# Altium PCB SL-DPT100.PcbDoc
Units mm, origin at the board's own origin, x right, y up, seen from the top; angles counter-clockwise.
Board outline 73.2 x 55.1 mm, 2 copper layers (Top Layer, Bottom Layer); 172 components, 163 nets, 580 pads, 6 vias.
Unrouted connection lines stored in the file: 382.
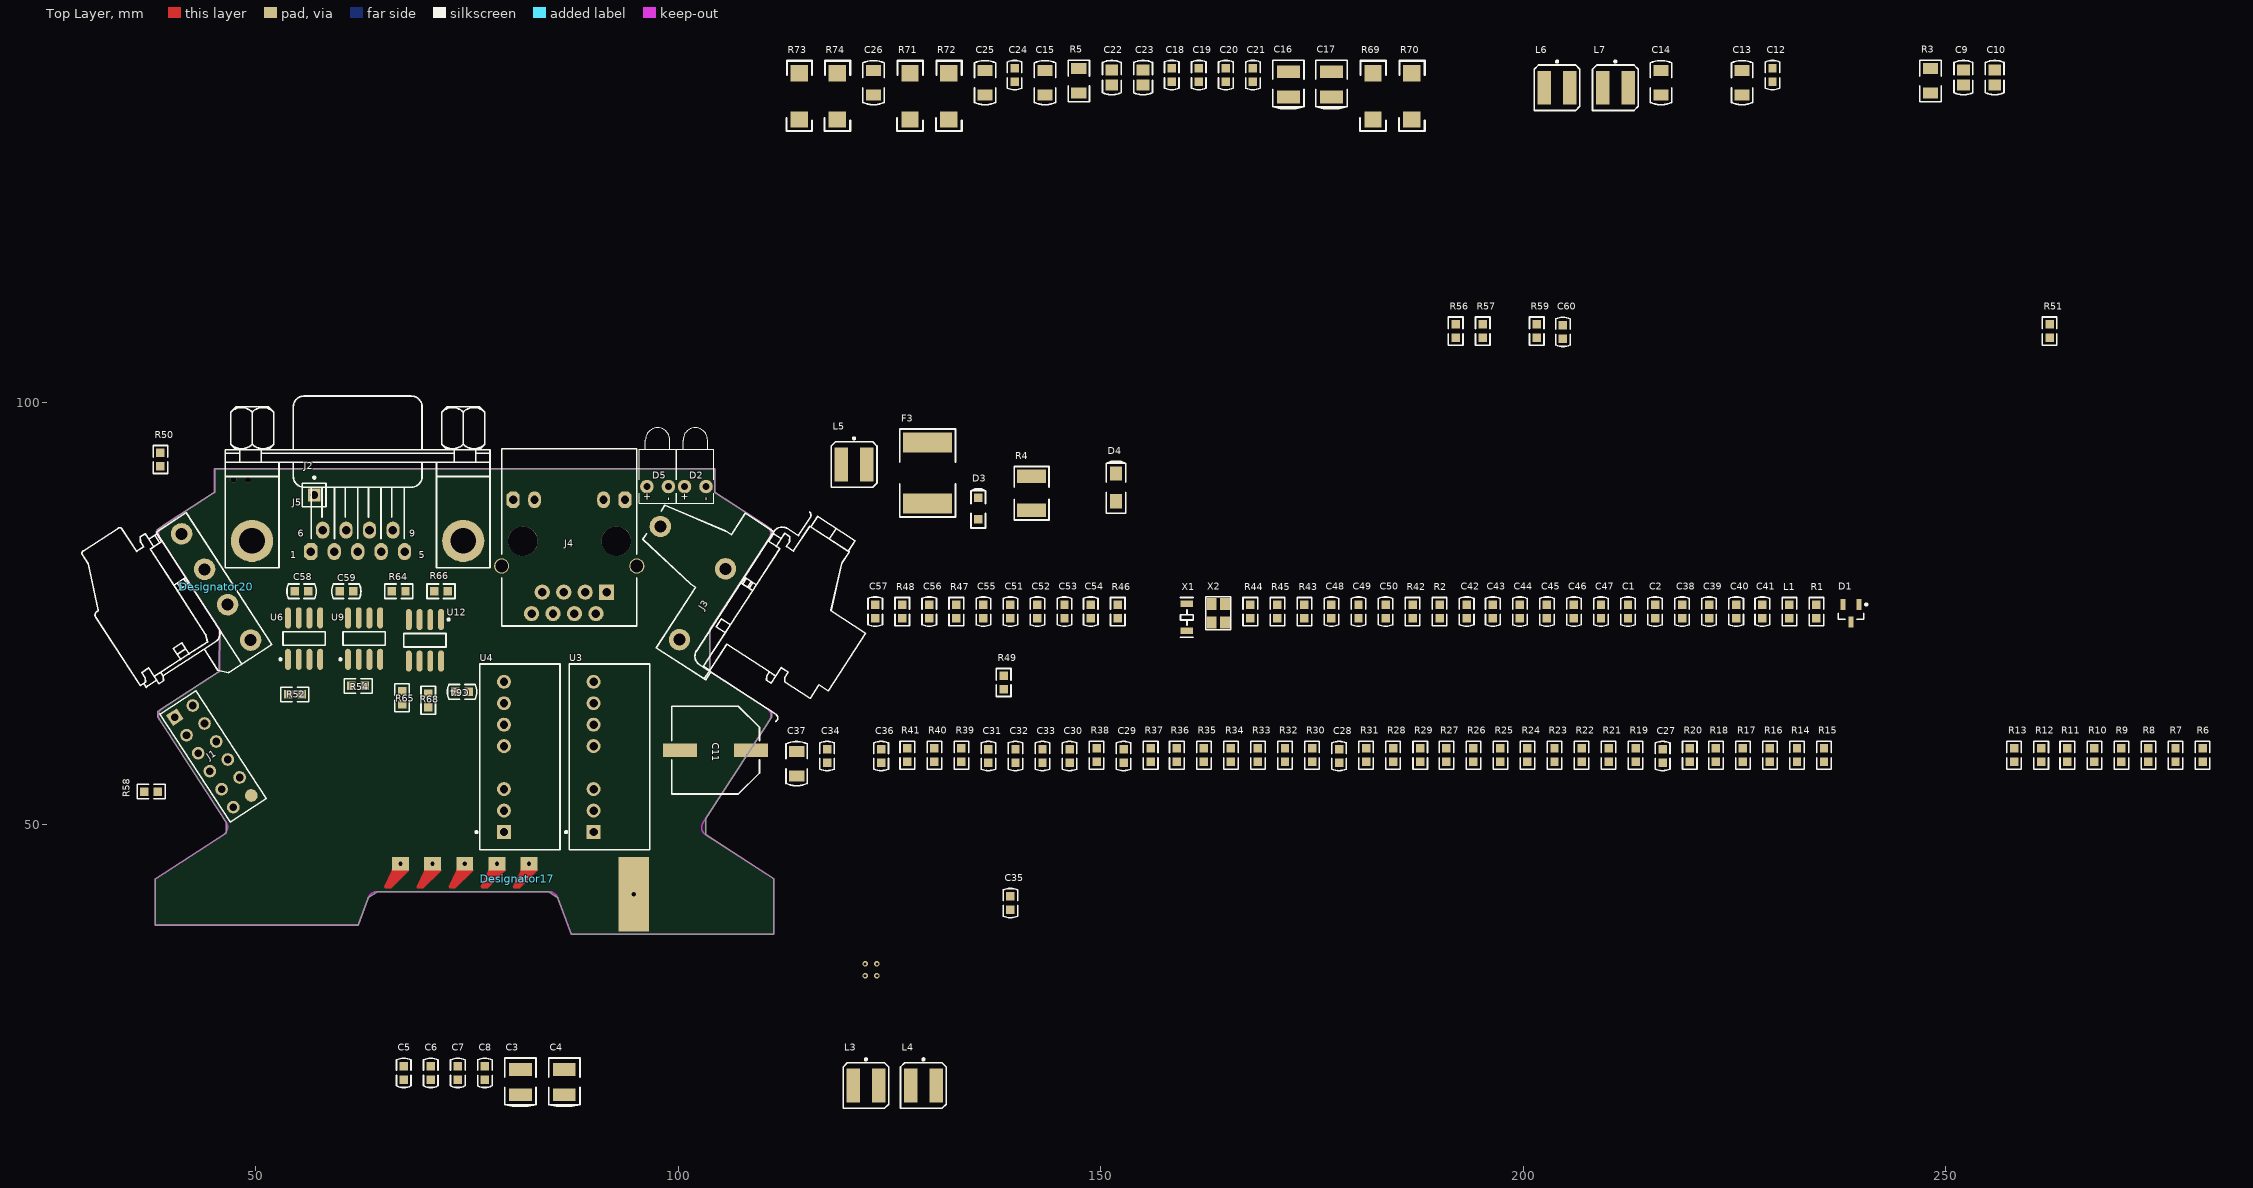
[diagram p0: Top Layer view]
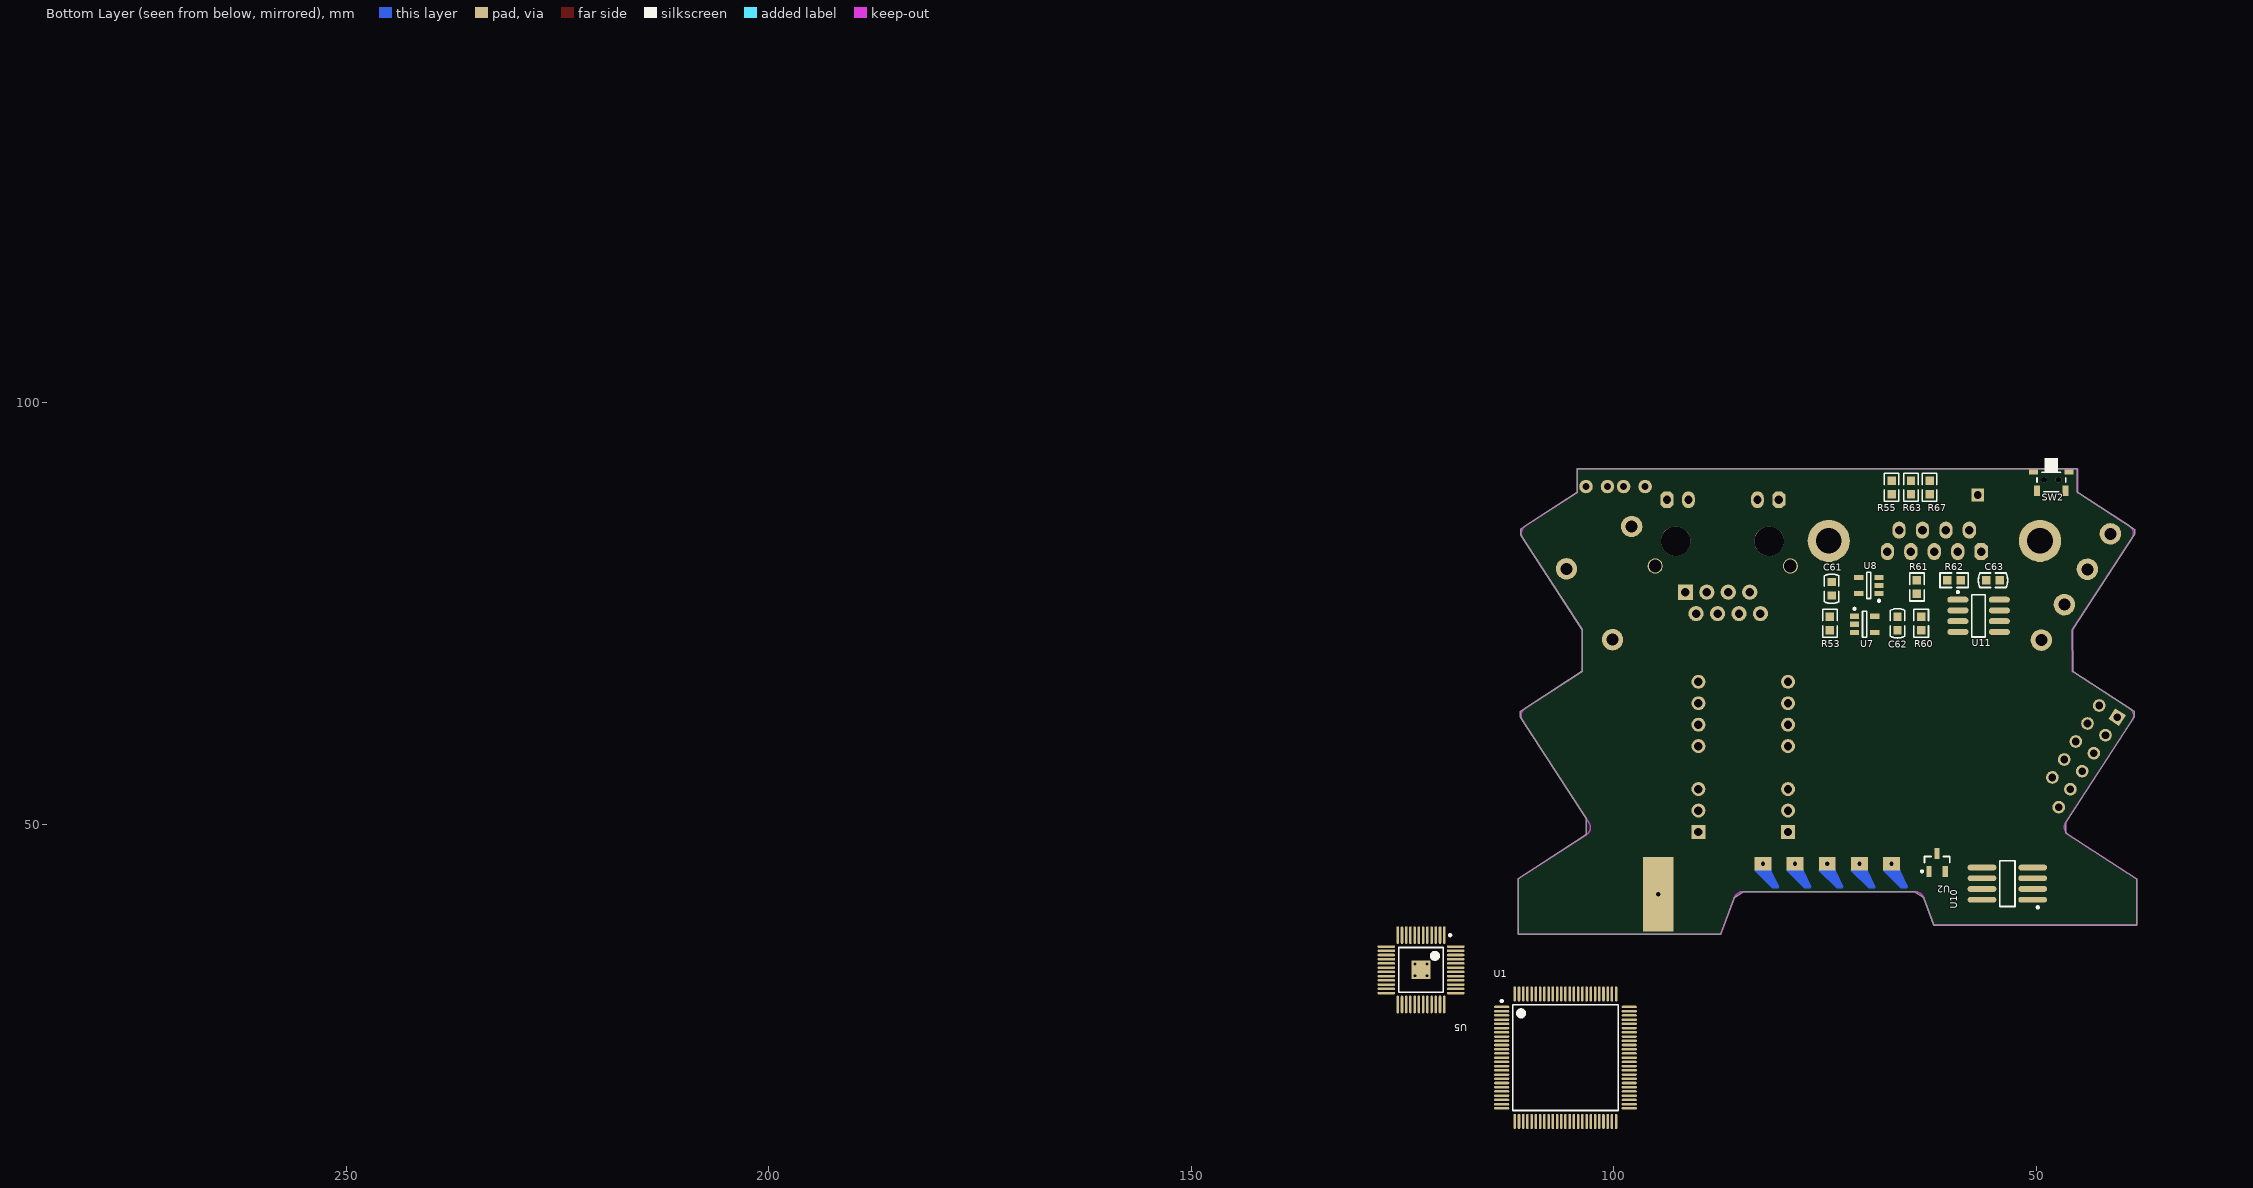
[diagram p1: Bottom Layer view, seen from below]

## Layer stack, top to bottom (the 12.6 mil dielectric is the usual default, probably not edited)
Top Layer: signal copper 0.0356
Dielectric: dielectric 0.32, FR-4, Dk 4.8
Bottom Layer: signal copper 0.0356

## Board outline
64.379,42.05 63.285,41.32 62.11,38.1 38.1,38.1 38.1,43.548 46.5,49 46.516,50.15 38.4,62.7 38.4,63.4 45.686,68.122 45.697,73.048 38.3,84.4 38.3,84.9 45.097,89.304 45.1,92.1 104.3,92.1 104.303,89.304 111,84.965 111,84.247 103.703,73.048 103.714,68.122 111.05,63.375 111.05,62.725 103.247,50.731 103.246,48.778 111.299,43.548 111.3,37 87.35,37 85.722,41.322 84.627,42.05

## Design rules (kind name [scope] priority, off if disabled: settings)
Clearance Clearance_U1_U5 [(InComponent(U1) Or InComponent(U5)) And IsComponentPad] p1: gap=0.2
Clearance Clearance_Pad_K [IsComponentPad vs OnLayer('Keep-Out Layer')] p2: gap=0.01
Clearance [All] p3: gap=0.254
HoleSize [All] p1: absolutevalues=TRUE maxlimit=25.4 minlimit=0.025 maxpercent=80.000 minpercent=20.000
PolygonConnect [All] p1: connectstyle=Relief reliefconductorwidth=0.254 reliefentries=4 polygonreliefangle="90 Angle"
RoutingVias [All] p1: holewidth=0.33 width=0.66 viastyle="Through Hole" minholewidth=0.305 minwidth=0.61 maxholewidth=3.048 maxwidth=6.096
SilkToSilkClearance [All] p1: silktosilkclearance=0.102
SilkscreenOverComponentPads SilkscreenOverComponentPads_1 [All] p1: minsilkscreentomaskgap=0.01
SilkscreenOverComponentPads [All] p2: minsilkscreentomaskgap=0.254
SolderMaskExpansion [All] p1: expansion=0.102
Width [All] p1: maxlimit=2.54 minlimit=0.152 preferedwidth=0.254
25 further rules are at their usual default settings.

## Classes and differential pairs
net class PE[0..15]: PE0 PE1 PE2 PE3 PE4 PE5 PE6 PE7 PE8 PE9 PE10 PE11 PE12 PE13 PE14 PE15
net class PD[0..15]: PD0 PD1 PD2 PD3 PD4 PD5 PD6 PD7 PD8 PD9 PD10 PD11 PD12 PD13 PD14 PD15
net class PC[0..15]: PC0 PC1 PC2 PC3 PC4 PC5 PC6 PC7 PC8 PC9 PC10 PC11 PC12 PC13 PC14 PC15
net class PB[0..15]: PB0 PB1 PB2 PB3 PB4 PB5 PB6 PB7 PB8 PB9 PB10 PB11 PB12 PB13 PB14 PB15
net class PA[0..15]: PA0 PA1 PA2 PA3 PA4 PA5 PA6 PA7 PA8 PA9 PA10 PA11 PA12 PA13 PA14 PA15
component class Power: C3 C4 C5 C6 C7 C8 C9 C10 C11 C12 C13 C14 C15 C16 C17 C18 C19 C20 C21 C22 C23 C24 C25 C26 D3 D4 F3 J3 L3 L4 L5 L6 L7 R3 R4 R5 R69 R70 R71 R72 R73 R74 U3 U4
component class MCU: C1 C2 C38 C39 C40 C41 C42 C43 C44 C45 C46 C47 C48 C49 C50 C51 C52 C53 C54 C55 C56 C57 D1 J1 L1 R1 R2 R42 R43 R44 R45 R46 R47 R48 R49 U2 X1 X2
component class MCU_1: C58 C59 C60 C61 C62 C63 C64 D2 D5 J2 J5 R50 R51 R52 R53 R54 R55 R56 R57 R58 R59 R60 R61 R62 R63 R64 R65 R66 R67 R68 SW2 U1 U6 U7 U8 U9 U10 U11 U12
component class Ethernet: C27 C28 C29 C30 C31 C32 C33 C34 C35 C36 C37 J4 R6 R7 R8 R9 R10 R11 R12 R13 R14 R15 R16 R17 R18 R19 R20 R21 R22 R23 R24 R25 R26 R27 R28 R29 R30 R31 R32 R33 R34 R35 R36 R37 R38 R39 R40 R41 U5

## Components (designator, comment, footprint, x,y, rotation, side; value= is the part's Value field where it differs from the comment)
C1 "0.1uF" C1608(0603) 212.4,75.2 r90 top
C2 "0.1uF" C1608(0603) 215.6,75.2 r90 top
C3 "33uF" C3528(B) 81.299,19.5 r90 top
C4 "33uF" C3528(B) 86.499,19.5 r90 top
C5 "0.01uF" C1608(0603) 67.499,20.6 r90 top
C6 "0.1uF" C1608(0603) 70.699,20.6 r90 top
C7 "0.01uF" C1608(0603) 73.899,20.6 r90 top
C8 "0.1uF" C1608(0603) 77.099,20.6 r90 top
C9 "4.7uF/50V" C2012(0805) 252.099,138.4 r90 top
C10 "4.7uF/50V" C2012(0805) 255.799,138.4 r90 top
C11 "330uF/50V" CAPMP10X120 104.4,58.8 r180 top
C12 "0.1uF" C1608(0603) 229.5,138.7 r90 top
C13 "10uF/50V" C3216(1206) 225.9,137.8 r90 top
C14 "1000pF/2KV" C3216(1206) 216.3,137.8 r90 top
C15 "1000pF/2KV" C3216(1206) 143.4,137.8 r90 top
C16 "33uF" C3528(B) 172.2,137.6 r90 top
C17 "33uF" C3528(B) 177.3,137.6 r90 top
C18 "0.01uF" C1608(0603) 158.4,138.7 r90 top
C19 "0.1uF" C1608(0603) 161.6,138.7 r90 top
C20 "0.01uF" C1608(0603) 164.8,138.7 r90 top
C21 "0.1uF" C1608(0603) 168,138.7 r90 top
C22 "4.7uF/50V" C2012(0805) 151.3,138.4 r90 top
C23 "4.7uF/50V" C2012(0805) 155,138.4 r90 top
C24 "0.1uF" C1608(0603) 139.8,138.7 r90 top
C25 "10uF/50V" C3216(1206) 136.3,137.8 r90 top
C26 "1000pF/2KV" C3216(1206) 123.1,137.8 r90 top
C27 "0.1uF" C1608(0603) 216.5,58.1 r90 top
C28 "0.1uF" C1608(0603) 178.2,58.1 r90 top
C29 "0.1uF" C1608(0603) 152.7,58.1 r90 top
C30 "22pF" C1608(0603) 146.3,58.1 r90 top
C31 "0.1uF" C1608(0603) 136.7,58.1 r90 top
C32 "0.1uF" C1608(0603) 139.9,58.1 r90 top
C33 "0.1uF" C1608(0603) 143.1,58.1 r90 top
C34 "0.1uF" C1608(0603) 117.6,58.1 r90 top
C35 "0.1uF" C1608(0603) 139.3,40.7 r90 top
C36 "0.1uF" C1608(0603) 124,58.1 r90 top
C37 "10uF" C3216(1206) 114,57.2 r90 top
C38 "0.1uF" C1608(0603) 218.8,75.2 r90 top
C39 "1uF" C1608(0603) 222,75.2 r90 top
C40 "0.1uF" C1608(0603) 225.2,75.2 r90 top
C41 "1uF" C1608(0603) 228.3,75.2 r90 top
C42 "0.1uF" C1608(0603) 193.3,75.2 r90 top
C43 "0.1uF" C1608(0603) 196.4,75.2 r90 top
C44 "0.1uF" C1608(0603) 199.6,75.2 r90 top
C45 "0.1uF" C1608(0603) 202.8,75.2 r90 top
C46 "0.1uF" C1608(0603) 206,75.2 r90 top
C47 "0.1uF" C1608(0603) 209.2,75.2 r90 top
C48 "0.1uF" C1608(0603) 177.3,75.2 r90 top
C49 "2.2uF" C1608(0603) 180.5,75.2 r90 top
C50 "2.2uF" C1608(0603) 183.7,75.2 r90 top
C51 "22pF" C1608(0603) 139.3,75.2 r90 top
C52 "22pF" C1608(0603) 142.5,75.2 r90 top
C53 "22pF" C1608(0603) 145.7,75.2 r90 top
C54 "22pF" C1608(0603) 148.8,75.2 r90 top
C55 "0.1uF" C1608(0603) 136.1,75.2 r90 top
C56 "1uF" C1608(0603) 129.7,75.2 r90 top
C57 "0.1uF" C1608(0603) 123.3,75.2 r90 top
C58 "0.1uF" C1608(0603) 55.4,77.6 r0 top
C59 "0.1uF" C1608(0603) 60.7,77.6 r180 top
C60 "0.1uF" C1608(0603) 204.7,108.3 r90 top
C61 "0.1uF" C1608(0603) 74.2,77.9 r270 bottom
C62 "0.1uF" C1608(0603) 66.4,73.81 r270 bottom
C63 "0.1uF" C1608(0603) 55.1,78.9 r0 bottom
C64 "0.1uF" C1608(0603) 74.4,65.7 r0 top
D1 "BAT54C" SOT23-3_N 238.8,75 r90 top
D2 "LED0" LED-1 102,90 r90 top locked
D3 "1A/30V" SOD323 135.5,87.4 r90 top
D4 "SMF24A" SOD123 151.8,89.9 r90 top
D5 "LED0" LED-1 97.55,90 r90 top locked
Designator17 "Comment" "ME22.5 TBUS1.5/5" 74.719,42.05 r0 top locked
Designator20 "Comment" "MKDSO 2.5/4-L" 45.285,78.11 r33 top locked
F3 "SMD2920P050" R7555(2920) 129.5,91.6 r90 top
J1 "H2.54 6X2" HDR2X6 40.4,62.7 r303 top locked
J2 "Plug" PIN1 56.9,89 r0 top
J3 "Header 3" "MKDSO2.5 HV/3R-7.5" 105.58,80.26 r327 top locked
J4 "HR911105A" RJ45-LED 91.5,77.5 r0 top locked
J5 "D Connector 9" DB9F 56.5,82.3 r0 top locked
L1 "FCM1608KF-601T03" R1608(0603) 231.5,75.2 r90 top
L3 "10uH/1A" L4040 122.199,19.1 r0 top
L4 "10uH/1A" L4040 128.999,19.1 r0 top
L5 "68uH/0.5A" L4040 120.8,92.6 r0 top
L6 "10uH/1A" L4040 204,137.2 r0 top
L7 "10uH/1A" L4040 210.9,137.2 r0 top
R1 "0R" R1608(0603) 234.7,75.2 r90 top
R2 "1K" R1608(0603) 190.1,75.2 r90 top
R3 "82R" R3216(1206) 248.2,138 r90 top
R4 "MLV1812NA030" R4532(1812) 141.8,89.2 r90 top
R5 "82R" R3216(1206) 147.4,138 r90 top
R6 "33R" R1608(0603) 280.399,58.2 r90 top
R7 "33R" R1608(0603) 277.199,58.2 r90 top
R8 "33R" R1608(0603) 273.999,58.2 r90 top
R9 "33R" R1608(0603) 270.799,58.2 r90 top
R10 "33R" R1608(0603) 267.599,58.2 r90 top
R11 "33R" R1608(0603) 264.399,58.2 r90 top
R12 "33R" R1608(0603) 261.299,58.2 r90 top
R13 "33R" R1608(0603) 258.099,58.2 r90 top
R14 "33R" R1608(0603) 232.4,58.2 r90 top
R15 "49.9R" R1608(0603) 235.6,58.2 r90 top
R16 "33R" R1608(0603) 229.2,58.2 r90 top
R17 "33R" R1608(0603) 226,58.2 r90 top
R18 "33R" R1608(0603) 222.8,58.2 r90 top
R19 "2.2K" R1608(0603) 213.3,58.2 r90 top
R20 "49.9R" R1608(0603) 219.7,58.2 r90 top
R21 "33R" R1608(0603) 210.1,58.2 r90 top
R22 "2.2K" R1608(0603) 206.9,58.2 r90 top
R23 "2.2K" R1608(0603) 203.7,58.2 r90 top
R24 "49.9R" R1608(0603) 200.5,58.2 r90 top
R25 "1K" R1608(0603) 197.3,58.2 r90 top
R26 "2.2K" R1608(0603) 194.1,58.2 r90 top
R27 "33R" R1608(0603) 190.9,58.2 r90 top
R28 "33R" R1608(0603) 184.6,58.2 r90 top
R29 "2.2K" R1608(0603) 187.8,58.2 r90 top
R30 "33R" R1608(0603) 175,58.2 r90 top
R31 "49.9R" R1608(0603) 181.4,58.2 r90 top
R32 "33R" R1608(0603) 171.8,58.2 r90 top
R33 "2.2K" R1608(0603) 168.6,58.2 r90 top
R34 "2.2K" R1608(0603) 165.4,58.2 r90 top
R35 "1K" R1608(0603) 162.2,58.2 r90 top
R36 "33R" R1608(0603) 159,58.2 r90 top
R37 "33R" R1608(0603) 155.9,58.2 r90 top
R38 "2.2K" R1608(0603) 149.5,58.2 r90 top
R39 "33R" R1608(0603) 133.5,58.2 r90 top
R40 "2.2K" R1608(0603) 130.3,58.2 r90 top
R41 "4.78K" R1608(0603) 127.1,58.2 r90 top
R42 "100R" R1608(0603) 186.9,75.2 r90 top
R43 "1M" R1608(0603) 174.1,75.2 r90 top
R44 "1K" R1608(0603) 167.7,75.2 r90 top
R45 "1M" R1608(0603) 170.9,75.2 r90 top
R46 "1K" R1608(0603) 152,75.2 r90 top
R47 "10R" R1608(0603) 132.9,75.2 r90 top
R48 "10K" R1608(0603) 126.5,75.2 r90 top
R49 "10K" R1608(0603) 138.5,66.8 r90 top
R50 "1K" R1608(0603) 38.7,93.2 r90 top
R51 "220R" R1608(0603) 262.299,108.4 r90 top
R52 "680R" R1608(0603) 54.6,65.4 r180 top
R53 "680R" R1608(0603) 74.4,73.81 r270 bottom
R54 "680R" R1608(0603) 62.1,66.4 r180 top
R55 "330R" R1608(0603) 67.1,89.9 r270 bottom
R56 "10K" R1608(0603) 192,108.4 r90 top
R57 "10K" R1608(0603) 195.2,108.4 r90 top
R58 "10K" R1608(0603) 37.6,53.9 r180 top
R59 "10K" R1608(0603) 201.6,108.4 r90 top
R60 "680R" R1608(0603) 63.6,73.81 r270 bottom
R61 "680R" R1608(0603) 64.1,78.1 r270 bottom
R62 "1K" R1608(0603) 59.7,78.9 r180 bottom
R63 "100K" R1608(0603) 64.8,89.9 r90 bottom
R64 "330R" R1608(0603) 66.9,77.6 r180 top
R65 "680R" R1608(0603) 67.3,65 r270 top
R66 "680R" R1608(0603) 71.9,77.6 r180 top
R67 "100K" R1608(0603) 62.6,89.9 r270 bottom
R68 "0R" R1608(0603) 70.4,64.7 r90 top
R69 "510K" TGR 182.1,136.2 r90 top
R70 "510K" TGR 186.7,136.2 r90 top
R71 "510K" TGR 127.3,136.2 r90 top
R72 "510K" TGR 131.9,136.2 r90 top
R73 "510K" TGR 114.2,136.2 r90 top
R74 "510K" TGR 118.7,136.2 r90 top
SW2 "SW-PB" Key2x4 48.2,90.8 r180 bottom locked
U1 "STM32F407VGT6" TQFP100_N 105.7,22.4 r180 bottom
U2 "MAX809TEUR" SOT23-3_N 61.7,45.5 r270 bottom
U3 "WRB2403S-3WR2" SIP8 92.5,58 r90 top
U4 "WRB2405S-3WR2" SIP8 81.9,58 r90 top
U5 "DP83848IVV" HLQFP48_M 122.8,32.8 r270 bottom
U6 "HCPL-060L" SO8_M 55.7,72 r90 top
U7 "SN74LVC1G132" SOT23-5_N 70.3,73.697 r180 bottom
U8 "SN74LVC1G132" SOT23-5_N 69.8,78.3 r0 bottom
U9 "HCPL-060L" SO8_M 62.8,72 r90 top
U10 "W25Q16DVSSI" SOIC8_M 53.4,43 r0 bottom
U11 "VP1176" SO8_M 56.8,74.7 r180 bottom
U12 "HCPL-060L" SO8_M 70,71.8 r270 top
X1 "32.768K" FC-135 160.2,74.5 r90 top
X2 "25MHz" XTAL-3225 163.9,75 r90 top

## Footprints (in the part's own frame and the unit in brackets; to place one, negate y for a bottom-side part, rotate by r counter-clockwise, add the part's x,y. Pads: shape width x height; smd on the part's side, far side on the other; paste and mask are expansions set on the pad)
C1608(0603) [mm] "Chip Capacitor, Body 1.6x0.8mm, IPC Medium Density"
  rect 1x1 smd: 1(-0.8,0) 2(0.8,0)
  silkscreen extent -1.73,-0.86 1.73,0.86, body extent -0.87,-0.48 0.87,0.48, height 0.85
C2012(0805) [mm] "Chip Capacitor, Body 2.0x1.3mm, IPC Medium Density"
  rect 1.3x1.5 smd: 1(-0.9,0) 2(0.9,0)
  silkscreen extent -2.03,-1.11 2.03,1.11, body extent -1.1,-0.72 1.1,0.72, height 1.1
C3216(1206) [mm] "Chip Capacitor, Body 3.2x1.6mm, IPC Medium Density"
  rect 1.3x1.8 smd: 1(-1.45,0) 2(1.45,0)
  Top Layer pour cut-out: -1.325,1.275 1.375,1.275 1.375,-1.275 -1.325,-1.275
  silkscreen extent -2.61,-1.26 2.61,1.26, body extent -1.7,-0.9 1.7,0.9, height 1.35
C3528(B) [mm] "Chip Capacitor, Body 3.5x2.8mm, IPC Medium Density"
  rect 1.5x2.7 smd: 1(-1.5,0) 2(1.5,0)
  Top Layer pour cut-out: -1.375,1.725 1.375,1.725 1.375,-1.725 -1.375,-1.725
  silkscreen extent -2.86,-1.86 2.86,1.86, body extent -1.7,-1.35 1.7,1.35, height 1.35
CAPMP10X120 [mm] "Molded Capacitor, 2-Leads, Body 10mmx12mm, IPC High Density"
  rect 4x1.6 smd: 1(-4.2,0) 2(4.2,0)
  silkscreen extent -5.2,-5.2 5.2,5.2, body extent -4.98,-5 4.98,4.98, height 12.1
DB9F [mil]
  oct 62x80 hole 40: 1(0,0)
  oval 62x80 hole 40: 2(109.17,0) 3(218.33,0) 4(327.5,0) 5(436.67,0) 6(55,100) 7(164.17,100) 8(273.33,100) 9(382.5,100)
  round 196.67 hole 120: 10(-274.17,50) 11(710,50)
  silkscreen extent -398,-75 835,725
FC-135 [mm]
  rect 0.75x1.5 smd: 1(-1.587,0.011) 2(1.613,0.011)
  silkscreen extent -2.33,-0.74 2.35,0.76
HDR2X6 [mm] "Connector; Header; 6x2 Position"
  rect 1.5x1.5 hole 0.9: 1(0,0)
  round 1.5 hole 0.9: 2(0,2.54) 3(2.54,0) 4(2.54,2.54) 5(5.08,0) 6(5.08,2.54) 7(7.62,0) 8(7.62,2.54) 9(10.16,0) 10(10.16,2.54) 11(12.7,0)
  round 1.5 smd: 12(12.7,2.54)
  silkscreen extent -1.27,-1.27 13.97,3.81
HLQFP48_M [mm] "48-Pin Thin Quad Flat Pack 0.5 mm Pitch, IPC Low Density"
  oval 2.1x0.3 smd: 1(-4.1,2.75) 2(-4.1,2.25) 3(-4.1,1.75) 4(-4.1,1.25) 5(-4.1,0.75) 6(-4.1,0.25) 7(-4.1,-0.25) 8(-4.1,-0.75) 9(-4.1,-1.25) 10(-4.1,-1.75) 11(-4.1,-2.25) 12(-4.1,-2.75) 25(4.1,-2.75) 26(4.1,-2.25) 27(4.1,-1.75) 28(4.1,-1.25) 29(4.1,-0.75) 30(4.1,-0.25) 31(4.1,0.25) 32(4.1,0.75) 33(4.1,1.25) 34(4.1,1.75) 35(4.1,2.25) 36(4.1,2.75)
  oval 0.3x2.1 smd: 13(-2.75,-4.1) 14(-2.25,-4.1) 15(-1.75,-4.1) 16(-1.25,-4.1) 17(-0.75,-4.1) 18(-0.25,-4.1) 19(0.25,-4.1) 20(0.75,-4.1) 21(1.25,-4.1) 22(1.75,-4.1) 23(2.25,-4.1) 24(2.75,-4.1) 37(2.75,4.1) 38(2.25,4.1) 39(1.75,4.1) 40(1.25,4.1) 41(0.75,4.1) 42(0.25,4.1) 43(-0.25,4.1) 44(-0.75,4.1) 45(-1.25,4.1) 46(-1.75,4.1) 47(-2.25,4.1) 48(-2.75,4.1)
  rect 2.2x2.2 smd: 49(0,0)
  silkscreen extent -4.22,-2.65 2.65,3.57, body extent -3.5,-3.5 3.5,3.5, height 1.6
Key2x4 [mm]
  rect 0.7x1.2 smd: 1(-1.7,-1.3) 2(1.7,-1.3)
  rect 1.1x0.7 smd: 3(2.1,0.95) 4(-2.1,0.95)
  silkscreen extent -1.7,-1.4 1.7,2.6
L4040 [mm] "Chip Inductor, Body 4.0x4.0mm, IPC Medium Density"
  rect 1.6x4 smd: 1(-1.5,0) 2(1.5,0)
  Top Layer pour cut-out: -1.438,2.375 1.438,2.375 1.438,-2.375 -1.438,-2.375
  silkscreen extent -2.7,-2.7 2.7,3.22, body extent -2,-2 2,2, height 0.71
LED-1 [mm] "Typical RED GaAs LED; 2 Leads"
  round 1.6 hole 0.8: 1(0,1.27) 2(0,-1.27)
  silkscreen extent -2,-2.2 6.95,2.2
"ME22.5 TBUS1.5/5" [mm]
  rect 2x1.6 hole 0.5: 1(-7.62,3.3) 2(-3.81,3.3) 3(0,3.3) 4(3.8,3.3) 5(7.6,3.3)
  rect 3.6x8.8 hole 0.5: 6(20,-0.3)
  Top Layer region: 1,2.6 1,2.5 -1.1,0.4 -1.8,0.4 -1.9,0.6 -1,2.5 -1,2.6
  Top Layer region: 4.8,2.6 4.8,2.5 2.7,0.4 2,0.4 1.9,0.6 2.8,2.5 2.8,2.6
  Top Layer region: 8.6,2.6 8.6,2.5 6.5,0.4 5.8,0.4 5.7,0.6 6.6,2.5 6.6,2.6
  Top Layer region: -2.81,2.6 -2.81,2.5 -4.91,0.4 -5.61,0.4 -5.71,0.6 -4.81,2.5 -4.81,2.6
  Top Layer region: -6.62,2.6 -6.62,2.5 -8.72,0.4 -9.42,0.4 -9.52,0.6 -8.62,2.5 -8.62,2.6
  Bottom Layer region: 1,2.6 1,2.5 -1.1,0.4 -1.8,0.4 -1.9,0.6 -1,2.5 -1,2.6
  Bottom Layer region: 4.8,2.6 4.8,2.5 2.7,0.4 2,0.4 1.9,0.6 2.8,2.5 2.8,2.6
  Bottom Layer region: 8.6,2.6 8.6,2.5 6.5,0.4 5.8,0.4 5.7,0.6 6.6,2.5 6.6,2.6
  Bottom Layer region: -2.81,2.6 -2.81,2.5 -4.91,0.4 -5.61,0.4 -5.71,0.6 -4.81,2.5 -4.81,2.6
  Bottom Layer region: -6.62,2.6 -6.62,2.5 -8.72,0.4 -9.42,0.4 -9.52,0.6 -8.62,2.5 -8.62,2.6
  Keep-Out Layer lines w0.2: -23,-3.95 -12.619,-3.95 -11.447,-0.729 ; -11.444,-0.73 cw(c-10.34,-1.2) -10.34,0 9.898,0 ; 9.898,0.002 cw(c9.898,-1.198) 11.002,-0.728 12.6,-5.05 23,-5.05
"MKDSO2.5 HV/3R-7.5" [mil]
  round 100 hole 56: 1(0,0) 2(-362.2,0) 3(-0.04,-393.74)
  silkscreen extent -398,-484 711,439
"MKDSO 2.5/4-L" [mm]
  round 2.54 hole 1.422: 1(0,2.5) 2(0,-2.5) 3(0,7.5) 4(0,-7.5)
  silkscreen extent -13.9,-9.3 1.8,12.15
PIN1 [mm] "Connector; Plug"
  rect 1.5x1.5 hole 0.9: 1(0,0)
  silkscreen extent -1.4,-1.4 1.4,2.17
R1608(0603) [mm] "Chip Resistor, Body 1.6x0.8mm, IPC Medium Density"
  rect 1x1 smd: 1(-0.8,0) 2(0.8,0)
  silkscreen extent -1.66,-0.86 1.66,0.86, body extent -0.87,-0.48 0.87,0.48, height 0.85
R3216(1206) [mm] "Chip Resistor, Body 3.2x1.6mm, IPC Medium Density"
  rect 1.3x1.8 smd: 1(-1.45,0) 2(1.45,0)
  Top Layer pour cut-out: -1.325,-1.275 -1.325,1.275 1.325,1.275 1.325,-1.275
  silkscreen extent -2.46,-1.26 2.46,1.26, body extent -1.7,-0.9 1.7,0.9, height 1.35
R4532(1812) [mm] "Chip Resistor, Body 4.5x3.2mm, IPC Medium Density"
  rect 1.6x3.4 smd: 1(-2,0) 2(2,0)
  Top Layer pour cut-out: -1.875,2.075 1.875,2.075 1.875,-2.075 -1.875,-2.075
  silkscreen extent -3.16,-2.06 3.16,2.06, body extent -2.4,-1.7 2.4,1.7, height 0.71
R7555(2920) [mm] "Chip Resistor, Body 7.5x5.5mm, IPC Medium Density"
  rect 2.4x5.8 smd: 1(-3.6,0) 2(3.6,0)
  Top Layer pour cut-out: -3.475,3.275 -3.475,-3.275 3.475,-3.275 3.475,3.275
  silkscreen extent -5.2,-3.3 5.2,3.3, body extent -3.75,-2.85 3.75,2.85, height 0.71
RJ45-LED [mm]
  round 3.5 hole 3.5: 0(-9.9,6.035) 0(1.16,6.035)
  rect 1.8x1.8 hole 1: 1(0.01,-0.005)
  round 1.8 hole 1: 2(-1.26,-2.545) 3(-2.53,-0.005) 4(-3.8,-2.545) 5(-5.07,-0.005) 6(-6.34,-2.545) 7(-7.61,-0.005) 8(-8.88,-2.545)
  oct 1.5x2 hole 0.991: 9(2.185,10.935) 12(-11.065,10.935)
  oval 1.5x2 hole 0.991: 10(-0.355,10.935) 11(-8.525,10.935)
  round 1.8 hole 1.5: 13(3.58,3.085) 14(-12.42,3.085)
  silkscreen extent -12.42,-4.02 3.58,16.98
SIP8 [mm] "SIP; 8 Round Pins; Body 22x9.5mm; Pitch 2.54 mm"
  rect 1.65x1.65 hole 1: 1(-8.89,2.54)
  round 1.65 hole 1: 2(-6.35,2.54) 3(-3.81,2.54) 5(1.27,2.54) 6(3.81,2.54) 7(6.35,2.54) 8(8.89,2.54)
  silkscreen extent -11,-4.1 11,5.92, body extent -11,-4.1 11,5.4, height 12
SO8_M [mm] "8-Pin Small Outline Integrated Circuit 1.27 mm Pitch, IPC Low Density"
  oval 2.5x0.7 smd: 1(-2.45,1.905) 2(-2.45,0.635) 3(-2.45,-0.635) 4(-2.45,-1.905) 5(2.45,-1.905) 6(2.45,-0.635) 7(2.45,0.635) 8(2.45,1.905)
  silkscreen extent -2.57,-2.5 0.8,2.93, body extent -2,-2.5 2,2.5, height 1.75
SOD123 [mm] "SOD-123; 2 Leads; Body 2.7 x 1.6 mm, (LxW)"
  rect 1.7x1.4 smd: 1(-1.65,0) 2(1.65,0)
  Top Layer pour cut-out: -0.8,1.1 -0.8,-1.1 0.8,-1.1 0.8,1.1
  silkscreen extent -3.06,-1.15 3.06,1.15, body extent -1.85,-0.91 1.85,0.9, height 1.35
SOD323 [mm] "SOD-323; 2 Leads; Body 2.5 x 1.3 mm, (LxW)"
  rect 1x1 smd: 1(-1.25,0) 2(1.25,0)
  Top Layer pour cut-out: -1.125,0.875 -1.125,-0.875 1.125,-0.875 1.125,0.875
  silkscreen extent -2.31,-0.86 2.31,0.86, body extent -1.25,-0.75 1.25,0.75, height 1.35
SOIC8_M [mm] "SOIC, 8-Leads, Body 5.4x5.4mm (max), Pitch 1.27mm, IPC Low Density"
  oval 3.4x0.7 smd: 1(-3,1.905) 2(-3,0.635) 3(-3,-0.635) 4(-3,-1.905) 5(3,-1.905) 6(3,-0.635) 7(3,0.635) 8(3,1.905)
  silkscreen extent -3.72,-2.7 0.9,2.93, body extent -2.69,-2.69 2.69,2.69, height 2.16
SOT23-3_N [mm] "SOT23, 3-Leads, Body 2.9x1.3mm, Pitch 0.95mm, Lead Span 2.3mm, IPC Medium Density"
  rect 1.3x0.6 smd: 1(1.05,-0.95) 2(1.05,0.95) 3(-1.05,0)
  silkscreen extent -0.7,-1.93 1.17,1.5, body extent -0.7,-1.5 0.7,1.5, height 1.2
SOT23-5_N [mm] "SOT23, 5-Leads, Body 2.9x1.6mm, Pitch 0.95mm, Lead Span 2.8mm, IPC Medium Density"
  rect 1.1x0.6 smd: 1(-1.2,0.95) 2(-1.2,0) 3(-1.2,-0.95) 4(1.2,-0.95) 5(1.2,0.95)
  silkscreen extent -1.33,-1.55 0.25,1.95, body extent -0.9,-1.55 0.9,1.55, height 1.45
TGR [mil]
  rect 75x80 smd: 1(-107.94,-4.4) 2(107.07,-4.4)
  silkscreen extent -163,-64 165,56
TQFP100_N [mm] "100-Pin Thin Quad Flat Pack 0.5 mm Pitch, IPC Medium Density"
  oval 1.8x0.3 smd: 1(-7.55,6) 2(-7.55,5.5) 3(-7.55,5) 4(-7.55,4.5) 5(-7.55,4) 6(-7.55,3.5) 7(-7.55,3) 8(-7.55,2.5) 9(-7.55,2) 10(-7.55,1.5) 11(-7.55,1) 12(-7.55,0.5) 13(-7.55,0) 14(-7.55,-0.5) 15(-7.55,-1) 16(-7.55,-1.5) 17(-7.55,-2) 18(-7.55,-2.5) 19(-7.55,-3) 20(-7.55,-3.5) 21(-7.55,-4) 22(-7.55,-4.5) 23(-7.55,-5) 24(-7.55,-5.5) 25(-7.55,-6) 51(7.55,-6) 52(7.55,-5.5) 53(7.55,-5) 54(7.55,-4.5) 55(7.55,-4) 56(7.55,-3.5) 57(7.55,-3) 58(7.55,-2.5) 59(7.55,-2) 60(7.55,-1.5) 61(7.55,-1) 62(7.55,-0.5) 63(7.55,0) 64(7.55,0.5) 65(7.55,1) 66(7.55,1.5) 67(7.55,2) 68(7.55,2.5) 69(7.55,3) 70(7.55,3.5) 71(7.55,4) 72(7.55,4.5) 73(7.55,5) 74(7.55,5.5) 75(7.55,6)
  oval 0.3x1.8 smd: 26(-6,-7.55) 27(-5.5,-7.55) 28(-5,-7.55) 29(-4.5,-7.55) 30(-4,-7.55) 31(-3.5,-7.55) 32(-3,-7.55) 33(-2.5,-7.55) 34(-2,-7.55) 35(-1.5,-7.55) 36(-1,-7.55) 37(-0.5,-7.55) 38(0,-7.55) 39(0.5,-7.55) 40(1,-7.55) 41(1.5,-7.55) 42(2,-7.55) 43(2.5,-7.55) 44(3,-7.55) 45(3.5,-7.55) 46(4,-7.55) 47(4.5,-7.55) 48(5,-7.55) 49(5.5,-7.55) 50(6,-7.55) 76(6,7.55) 77(5.5,7.55) 78(5,7.55) 79(4.5,7.55) 80(4,7.55) 81(3.5,7.55) 82(3,7.55) 83(2.5,7.55) 84(2,7.55) 85(1.5,7.55) 86(1,7.55) 87(0.5,7.55) 88(0,7.55) 89(-0.5,7.55) 90(-1,7.55) 91(-1.5,7.55) 92(-2,7.55) 93(-2.5,7.55) 94(-3,7.55) 95(-3.5,7.55) 96(-4,7.55) 97(-4.5,7.55) 98(-5,7.55) 99(-5.5,7.55) 100(-6,7.55)
  silkscreen extent -7.68,-6.25 6.25,6.82, body extent -7,-7 7,7, height 1.6
XTAL-3225 [mm]
  rect 1.4x1.15 smd: 1(-1.108,-0.802) 2(1.092,-0.802) 3(1.092,0.798) 4(-1.108,0.798)
  silkscreen extent -1.96,-1.5 1.94,1.5

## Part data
C1 C2 C5 C6 C7 C8 C9 C10 C12 C14 C15 C18 C19 C20 C21 C22 C23 C24 C26 C27 C28 C29 C30 C31 C32 C33 C34 C35 C36 C38 C39 C40 C41 C42 C43 C44 C45 C46 C47 C48 C49 C50 C51 C52 C53 C54 C55 C56 C57 C58 C59 C60 C61 C62 C63 C64: library part CAP, "Capacitor"
C3 C4 C11 C16 C17: library part "CAPACITOR POL", "CA45-?V?uF ABCD 16V10UF[A型3210]16V22UF(B型1210) 16V47UF(C型1812)"
C13 C25 C37: library part "Cap Pol2", "Polarized Capacitor (Axial)"
D2 D5: "Typical INFRARED GaAs LED"
D3: library part Diode, "Default Diode"
D4: library part "D Zener", "Zener Diode"
F3: library part FUSE1, "Fuse"
J1: library part "Header 6X2", "Header, 6-Pin, Dual row"
J3: "Header, 3-Pin"
J5: "Receptacle Assembly, 9 Position, Right Angle"
L1 L3 L4 L5 L6 L7: library part Inductor, "Inductor"
R1 R2 R3 R5 R42 R43 R44 R45 R46 R47 R48 R49 R69 R70 R71 R72 R73 R74: library part R
R4: library part "Res Varistor", "Varistor (Voltage-Sensitive Resistor)"
R6 R7 R8 R9 R10 R11 R12 R13 R14 R15 R16 R17 R18 R19 R20 R21 R22 R23 R24 R25 R26 R27 R28 R29 R30 R31 R32 R33 R34 R35 R36 R37 R38 R39 R40 R41 R50 R51 R52 R53 R54 R55 R56 R57 R58 R59 R60 R61 R62 R63 R64 R65 R66 R67 R68: library part "Res Semi", "Semiconductor Resistor"
SW2: "Switch"
U1: "ARM Cortex-M4 32b MCU+FPU, 210DMIP, 1024 kB Flash, 192+4 kB RAM, Camera, 82 I/Os, 100-pin LQFP, -40 to +85癈, Tray"
U2: library part MAX6520EUR-T, "3-Terminal, 1.2V Voltage Reference"
U3 U4: library part WRA_S-1WR2
U5: library part DP83848CVV
U6 U9 U12: library part HCPL-060
U10: library part 25AA640A-I/SN, "64K SPI Bus Serial EEPROM, 8-Pin SOIC, Industrial Temperature"
U11: library part MAX485ESA, "Low-Power, Slew-Rate-Limited RS-485/RS-422 Transceiver"
X1 X2: library part CRYSTAL

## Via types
v1: diameter 0.66, hole 0.33, Top Layer to Bottom Layer, tented both sides, 4 vias
v2: diameter 0.7, hole 0.7, Top Layer to Bottom Layer, tented both sides, 2 vias

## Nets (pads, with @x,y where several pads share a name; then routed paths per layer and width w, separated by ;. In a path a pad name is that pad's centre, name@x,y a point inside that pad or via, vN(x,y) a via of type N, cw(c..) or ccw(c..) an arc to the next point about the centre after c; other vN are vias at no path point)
BOOT0: R2.1 R42.2 U1.94
BOOT_0: J1.5 R42.1
DE: R60.2 U7.4 U11.3
DE#: R53.1 U6.6 U7.1
DP-A: J5.3 R63.1 U11.6
DP-B: J5.8 R67.2 U11.7
ETH_RD+: J4.3 R24.1 U5.14
ETH_RD-: J4.6 R31.1 U5.13
ETH_TD+: J4.1 R15.1 U5.17
ETH_TD-: J4.2 R20.1 U5.16
GND: C1.2 C2.2 C3.2 C4.2 C5.1 C6.1 C7.1 C8.1 C13.2 C14.1 C27.2 C28.2 C29.2 C30.1 C31.1 C32.1 C33.1 C34.1 C35.1 C36.1 C37.2 C38.2 C39.2 C40.2 C41.2 C42.2 C43.2 C44.2 C45.2 C46.2 C47.2 C48.2 C49.2 C50.2 C51.1 C52.1 C53.1 C54.1 C55.2 C56.2 C57.1 C60.2 C64.2 J1.1 J1.2 J4.8 R2.2 R3.2 R40.2 R41.2 R44.1 R49.1 R52.1 R69.1 SW2.2 U1.10 U1.20 U1.27 U1.74 U1.99 U2.1 U3.7 U5.15 U5.19 U5.35 U5.36 U5.47 U5.49 U10.4 U12.5
  other v1: 122.1,32.1 123.5,32.1 122.1,33.5 123.5,33.5
GNDD: C15.1 C16.2 C17.2 C18.1 C19.1 C20.1 C21.1 C25.2 C58.2 C59.2 C61.1 C62.2 C63.2 J5.5 R5.2 R60.1 R62.2 R67.1 R71.1 U4.7 U6.5 U7.3 U8.3 U9.5 U11.5
GNDE: C14.2 C15.2 C26.2 J3.2 J4.13 J4.14 J5.1 J5.10 J5.11 R70.2 R72.2 R74.2
LED_ACT: R26.2 R35.2 U5.26
LED_LINK: R19.2 R25.2 U5.28
NetC12_1: C12.1 U3.3
NetC13_1: C13.1 U3.8
NetC24_1: C24.1 U4.3
NetC25_1: C25.1 U4.8
NetC30_2: C30.2 U5.33
NetC34_2: C34.2 C35.2 C36.2 C37.1 U5.18 U5.23 U5.37
NetC49_1: C49.1 U1.49
NetC50_1: C50.1 U1.73
NetD2_2: D2.2 R51.2
NetD5_1: D5.1 R55.2
NetD5_2: D5.2 U8.4
NetJ1_10: J1.10 J1.11 R47.1
NetJ4_10: J4.10 R25.1
NetJ4_11: J4.11 R35.1
NetR6_1: R6.1 U5.1
NetR7_1: R7.1 U5.2
NetR8_1: R8.1 U5.3
NetR9_1: R9.1 U5.4
NetR10_1: R10.1 U5.5
NetR11_1: R11.1 U5.6
NetR12_1: R12.1 U5.43
NetR13_1: R13.1 U5.44
NetR14_1: R14.1 U5.45
NetR16_1: R16.1 U5.46
NetR17_1: R17.1 U5.41
NetR18_1: R18.1 U5.38
NetR21_1: R21.1 R23.1 U5.39
NetR22_2: R22.2 U5.27
NetR27_1: R27.1 U5.42
NetR28_1: R28.1 U5.40
NetR29_2: R29.2 U5.21
NetR30_1: R30.1 U5.31
NetR32_1: R32.1 R34.1 U5.30
NetR33_2: R33.2 U5.20
NetR36_1: R36.1 U5.29
NetR37_1: R37.1 R38.1 U5.7
NetR39_1: R39.1 U5.34
NetR40_1: R40.1 U5.25
NetR41_1: R41.1 U5.24
NetR46_2: R46.2 U2.2
NetR50_2: R50.2 SW2.1
NetR52_2: R52.2 U6.3
NetR54_2: R54.2 U9.2
NetR64_1: R64.1 R66.2 U12.2
NetR69_2: R69.2 R70.1
NetR71_2: R71.2 R72.1
NetR73_2: R73.2 R74.1
OSC_IN: C54.2 R43.1 U1.12 X2.1
OSC_OUT: C53.2 R43.2 U1.13 X2.3
PA0: R28.2 U1.23
PA1: R18.2 U1.24
PA2: R32.2 U1.25
PA3: R27.2 U1.26
PA4: U1.29
PA5: R50.1 U1.30
PA6: R51.1 U1.31
PA7: R21.2 U1.32
PA8: R39.2 U1.67
PA9: J1.7 U1.68
PA10: J1.9 U1.69
PA11: U1.70
PA12: U1.71
PA13: J1.8 R48.2 U1.72
PA14: J1.6 R49.2 U1.76
PA15: R59.1 U1.77 U10.1
PB0: R14.2 U1.35
PB1: R16.2 U1.36
PB2: R44.2 U1.37
PB3: R58.1 U1.89 U10.6
PB4: R56.1 U1.90 U10.2
PB5: R57.1 U1.91 U10.5
PB6: U1.92
PB7: U1.93
PB8: R11.2 U1.95
PB9: U1.96
PB10: R17.2 U1.47
PB11: R7.2 U1.48
PB12: R8.2 U1.51
PB13: R9.2 U1.52
PB14: U1.53
PB15: U1.54
PC0: R37.2 U1.15
PC1: R30.2 U1.16
PC2: R10.2 U1.17
PC3: R6.2 U1.18
PC4: R12.2 U1.33
PC5: R13.2 U1.34
PC6: U1.63 U9.3
PC7: R65.1 R68.2 U1.64 U12.6
PC8: R68.1 U1.65
PC9: U1.66 U6.2
PC10: U1.78
PC11: U1.79
PC12: U1.80
PC13: J2.1 U1.7
PC14: C51.2 R45.2 U1.8 X1.2
PC15: C52.2 R45.1 U1.9 X1.1
PD0: U1.81
PD1: U1.82
PD2: U1.83
PD3: U1.84
PD4: U1.85
PD5: U1.86
PD6: U1.87
PD7: U1.88
PD8: U1.55
PD9: U1.56
PD10: U1.57
PD11: U1.58
PD12: U1.59
PD13: U1.60
PD14: U1.61
PD15: U1.62
PE0: U1.97
PE1: U1.98
PE2: U1.1
PE3: U1.2
PE4: U1.3
PE5: U1.4
PE6: U1.5
PE7: U1.38
PE8: U1.39
PE9: U1.40
PE10: U1.41
PE11: U1.42
PE12: U1.43
PE13: U1.44
PE14: U1.45
PE15: U1.46
RE#: R62.1 U11.2
RST#: C48.1 R36.2 R46.1 R47.2 U1.14
RXD: R66.1 U8.2 U11.1 U12.3
TXD: R61.1 U8.1 U9.6 U11.4
V3.3: C4.1 C7.2 C8.2 C27.1 C28.1 C29.1 C31.2 C32.2 C33.2 C42.1 C43.1 C44.1 C45.1 C46.1 C47.1 C55.1 C56.1 C57.2 C60.1 C64.1 D1.2 D2.1 J1.3 J1.4 J4.4 J4.5 J4.9 J4.12 L1.2 L4.2 R15.2 R19.1 R20.2 R22.1 R23.2 R24.2 R26.1 R29.1 R31.2 R33.1 R34.2 R38.2 R48.1 R54.1 R56.2 R57.2 R58.2 R59.2 R65.2 U1.11 U1.19 U1.28 U1.50 U1.75 U1.100 U2.3 U5.22 U5.32 U5.48 U10.3 U10.7 U10.8 U12.7 U12.8
V3.3_1: C3.1 C5.2 C6.2 L4.1 R3.1 U3.6
V5.0: C17.1 C20.2 C21.2 C58.1 C59.1 C61.2 C62.1 C63.1 J5.6 L7.2 R53.2 R55.1 R61.2 R63.2 R64.2 U6.7 U6.8 U7.2 U7.5 U8.5 U9.7 U9.8 U11.8
V5.0_1: C16.1 C18.2 C19.2 L7.1 R5.1 U4.6
V24+: F3.1 J3.3
V24+1: D3.1 F3.2 R4.1
V24+2: D3.2 D4.2 L5.2
V24+3: C9.2 C11.1 C22.2 L3.1 L5.1 L6.1
V24+4: C10.2 L3.2 U3.2
V24+5: C23.2 L6.2 U4.2
V24-: C9.1 C10.1 C11.2 C12.2 C22.1 C23.1 C24.2 C26.1 D4.1 J3.1 R4.2 R73.1 U3.1 U4.1
V_BAT: C1.1 D1.1
VBAT: C2.1 D1.3 U1.6
VDDA: C40.1 C41.1 L1.1 R1.1 U1.22
VREF+: C38.1 C39.1 R1.2 U1.21
pads on no net: Designator17.1 Designator17.2 Designator17.3 Designator17.4 Designator17.5 Designator17.6 Designator20.1 Designator20.2 Designator20.3 Designator20.4 J1.12 J4.0 J4.7 J5.2 J5.4 J5.7 J5.9 SW2.3 SW2.4 U3.5 U4.5 U5.8 U5.9 U5.10 U5.11 U5.12 U6.1 U6.4 U9.1 U9.4 U12.1 U12.4 X2.2 X2.4
copper on no net:
  other v2: 47.35,90.8 49.05,90.8

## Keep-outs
Keep-Out Layer:
  lines w0.2: 38.1,43.548 38.1,38.1 62.1,38.1 ; 38.101,43.548 46.154,48.778 ; 38.583,62.381 cw(c39.449,62.881) 38.949,63.747 45.686,68.122 ; 38.586,62.383 46.526,50.157 ; 45.097,89.304 38.975,85.329 ccw(c39.475,84.463) 38.609,83.963 45.697,73.048 45.697,68.103 ; 45.1,89.304 45.1,92.1 104.3,92.1 ; 46.15,48.784 ccw(c45.65,49.65) 46.516,50.15 ; 62.11,38.1 63.282,41.321 ; 63.285,41.32 cw(c64.389,40.85) 64.389,42.05 84.627,42.05 ; 84.627,42.052 cw(c84.627,40.852) 85.731,41.322 87.329,37 ; 87.35,37 111.3,37 111.3,43.55 ; 102.874,50.157 110.814,62.383 ; 102.884,50.15 ccw(c103.75,49.65) 103.25,48.784 ; 103.246,48.778 111.299,43.548 ; 103.703,68.103 103.703,73.048 110.791,83.963 ccw(c109.925,84.463) 110.425,85.329 104.303,89.304 ; 103.714,68.122 110.451,63.747 cw(c109.951,62.881) 110.817,62.381 ; 104.3,89.304 104.3,92.1 ; 104.3,92.1 104.3,92.1

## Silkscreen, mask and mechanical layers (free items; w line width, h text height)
Mechanical 15:
  drawing of 235 lines, arcs and shapes, not listed

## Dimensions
45.1,92.6 to 104.3,92.6 on Mechanical 1
41.2,60.4 to 108.2,56.9 on Mechanical 1
38.1,86.2 to 111.3,92.6 on Mechanical 1
37.65,84.75 to 44.6,92.1 on Mechanical 1
37.7,38.15 to 34.6,92.1 on Mechanical 1
37.75,63.2 to 37.6,92.1 on Mechanical 1
37.6,43.55 to 37.6,92.1 on Mechanical 1
44.767,68 to 37.3,63.093 on Mechanical 1
39.55,62.75 to 104.6,92.1 on Mechanical 1
39.28,84.35 to 104.6,92.1 on Mechanical 1
87.35,36.3 to 111.3,36.32 on Mechanical 1
111.8,37 to 104.6,92.1 on Mechanical 1
38.1,37.8 to 111.3,36.6 on Mechanical 1
45.7,73.7 to 103.7,73.8 on Mechanical 1
38.1,37.7 to 62.1,37.6 on Mechanical 1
